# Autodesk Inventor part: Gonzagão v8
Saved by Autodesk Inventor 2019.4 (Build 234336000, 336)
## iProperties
Created: 2020-03
Part Number: Gonzagão v8
Material: Generic
Document SubType Name: Modeling
Designer: Administrator
Density: 1 g/cm^3
Appearance: Default
Author: Administrator
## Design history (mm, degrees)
feature "Estrutura dir" [Guia]
feature "Estrutura esq" [Guia]
feature "Pistao dir" [Guia]
feature "Guia 1"
feature "Guia 2"
feature "Guia 3"
feature "Guia 4"
feature "Plate castanha" [Guia]
feature "Fuso" [Guia]
feature "Ambu" [Guia]
feature "Parafuso M3 x 12 (2)" [Guia]
feature "Parafuso M3 x 12 (1)" [Guia]
feature "Parafuso M3 x 12 (4)" [Guia]
feature "Parafuso M3 x 16 (1)" [Guia]
feature "Parafuso M3 x 16 (2)" [Guia]
feature "Pistao dir (1)" [Guia]
feature "Plate suporte pistao" [Guia]
feature "Body33" [Guia]
feature "Body36" [Guia]
body "Solid1"
body "Solid2"
body "Solid3"
body "Solid4"
body "Solid5"
body "Solid6"
body "Solid7"
body "Solid8"
body "Solid9"
body "Solid10"
body "Solid11"
body "Solid12"
body "Solid13"
body "Solid14"
body "Solid15"
body "Solid16"
body "Solid17"
body "Solid18"
body "Solid19"
